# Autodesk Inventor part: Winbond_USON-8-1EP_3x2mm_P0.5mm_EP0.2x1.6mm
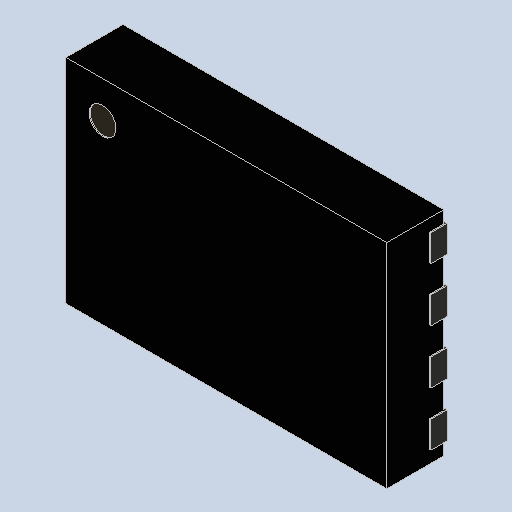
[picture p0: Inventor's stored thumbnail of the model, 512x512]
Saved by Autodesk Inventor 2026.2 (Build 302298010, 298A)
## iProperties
Created: 2026-10
Part Number: Winbond_USON-8-1EP_3x2mm_P0.5mm_EP0.2x1.6mm
Material: Générique
Document SubType Name: Modeling
Designer: mel
Density: 1 g/cm^3
Appearance: Par défaut
Author: mel
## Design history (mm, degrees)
feature "Base1"
node "Solide1"
